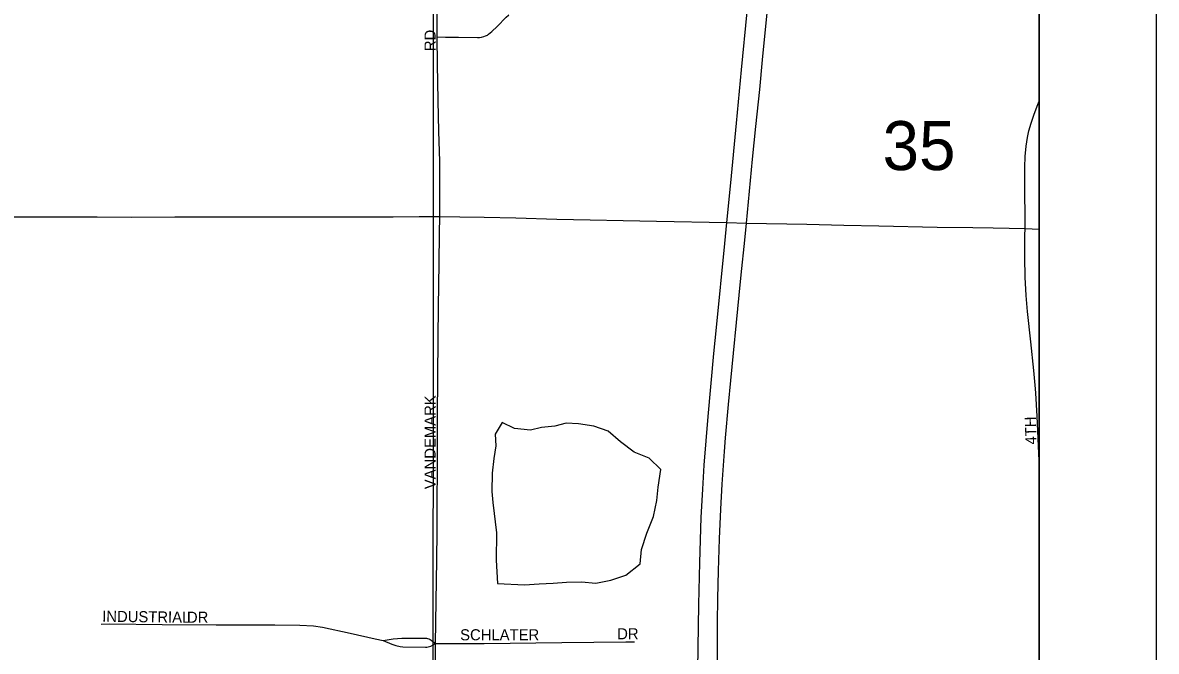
# Model space of a CAD drawing. Extents: x 0 to 1391, y -24 to 440.
# Drawn here: x 460.63 to 480, y 332.13 to 342.87 of the extents above; entities that cross this region are included whole.
import ezdxf

# ---------------------------------------------------------------- set-up
doc = ezdxf.new("R2010")
doc.units = 0
for name, color, linetype in [('GM_X_City_Street', 7, 'Continuous'), ('GM_X_City_Street_Text', 7, 'Continuous'), ('GM_X_Corporation', 7, 'Continuous'), ('GM_X_Interstate_Route', 7, 'Continuous'), ('GM_X_Minor_Lake', 7, 'Continuous'), ('GM_X_Section', 7, 'Continuous'), ('GM_X_Section_Text', 7, 'Continuous'), ('GM_X_Township', 7, 'Continuous'), ('SH_Data', 7, 'Continuous')]:
    doc.layers.add(name, color=color, linetype=linetype)

msp = doc.modelspace()

# ---------------------------------------------------------------- linework, layer by layer
at = {"layer": 'GM_X_City_Street'}
for points in [[(467.717, 342.622), (467.717, 343.089)], [(467.717, 342.622), (467.859, 342.62), (468.078, 342.616), (468.404, 342.611), (468.439, 342.612), (468.471, 342.616), (468.51, 342.627), (468.543, 342.639), (468.573, 342.654), (468.594, 342.668), (468.65, 342.712), (468.74, 342.797), (468.895, 342.96), (468.935, 342.994), (468.941, 342.997)], [(467.761, 339.554), (467.762, 339.75), (467.76, 340.046), (467.758, 340.5), (467.744, 341.008), (467.734, 341.536), (467.722, 342.157), (467.717, 342.616), (467.717, 342.622)], [(477.757, 339.347), (477.758, 339.525), (477.753, 339.997), (477.754, 340.395), (477.762, 340.582), (477.778, 340.757), (477.8, 340.905), (477.824, 341.015), (477.86, 341.148), (477.911, 341.303), (477.974, 341.466), (478, 341.523)], [(459.98, 339.55), (460.352, 339.55), (460.948, 339.551), (461.483, 339.549), (461.906, 339.546), (462.489, 339.542), (463.234, 339.548), (464.689, 339.549), (465.111, 339.548), (465.608, 339.547), (466.962, 339.551), (467.41, 339.554), (467.761, 339.554)], [(467.688, 332.258), (467.7, 332.981), (467.708, 333.682), (467.713, 334.18), (467.72, 335.738), (467.723, 336.135), (467.73, 337.48), (467.736, 338.01), (467.748, 338.755), (467.755, 339.262), (467.761, 339.554)], [(467.761, 339.554), (468.101, 339.551), (468.516, 339.543), (469.058, 339.531), (469.757, 339.511), (471.459, 339.475), (472.665, 339.45), (472.999, 339.443), (474.031, 339.425), (474.664, 339.408), (475.261, 339.394), (476.254, 339.374), (476.864, 339.364), (477.21, 339.363), (477.757, 339.347)], [(477.942, 336.538), (477.938, 336.612), (477.91, 336.921), (477.857, 337.415), (477.801, 337.934), (477.778, 338.207), (477.762, 338.518), (477.754, 338.854), (477.756, 339.227), (477.757, 339.347)], [(477.757, 339.347), (478, 339.337)], [(478, 335.321), (477.998, 335.381), (477.964, 336.141), (477.942, 336.538)], [(461.975, 332.591), (462.123, 332.594), (463.017, 332.583), (463.937, 332.579), (464.944, 332.58), (465.366, 332.576), (465.6, 332.561), (465.758, 332.539), (466.231, 332.436), (466.657, 332.343), (466.795, 332.312)], [(466.795, 332.312), (466.965, 332.34), (467.113, 332.352), (467.306, 332.351), (467.509, 332.351), (467.53, 332.35), (467.548, 332.346), (467.572, 332.338), (467.595, 332.328), (467.611, 332.318), (467.688, 332.258)], [(466.795, 332.312), (466.94, 332.25), (467.01, 332.226), (467.082, 332.209), (467.131, 332.204), (467.513, 332.199), (467.537, 332.2), (467.559, 332.203), (467.585, 332.21), (467.604, 332.216), (467.688, 332.258)], [(467.663, 329.897), (467.672, 330.736), (467.675, 331.091), (467.688, 332.246), (467.688, 332.258)], [(467.688, 332.258), (467.782, 332.258), (468.515, 332.261), (469.845, 332.279), (470.938, 332.288), (471.087, 332.288)]]:
    msp.add_lwpolyline(points, dxfattribs=at)
at = {"layer": 'GM_X_Corporation'}
msp.add_line((478, 308.53), (478, 378.802), dxfattribs=at)
at = {"layer": 'GM_X_Interstate_Route'}
for points in [[(472.17, 331.818), (472.183, 332.924), (472.199, 333.644), (472.226, 334.414), (472.251, 334.897), (472.278, 335.306), (472.345, 336.136), (472.441, 337.213), (472.485, 337.658), (472.63, 339.092), (472.665, 339.45), (472.731, 340.131), (472.827, 341.146), (472.913, 342.062), (473.013, 343.051)], [(472.501, 331.638), (472.502, 332.135), (472.505, 332.62), (472.511, 333.03), (472.52, 333.502), (472.536, 334.049), (472.561, 334.558), (472.584, 334.98), (472.623, 335.539), (472.641, 335.774), (472.691, 336.344), (472.73, 336.752), (472.874, 338.211), (472.91, 338.557), (472.969, 339.151), (472.999, 339.443), (473.102, 340.536), (473.158, 341.093), (473.224, 341.723), (473.275, 342.23), (473.35, 343.034)]]:
    msp.add_lwpolyline(points, dxfattribs=at)
at = {"layer": 'GM_X_Minor_Lake'}
for points in [[(468.746, 333.288), (469.208, 333.265), (469.459, 333.282), (469.695, 333.293), (469.923, 333.311), (470.182, 333.313), (470.425, 333.293), (470.684, 333.341), (470.936, 333.427), (471.183, 333.619), (471.203, 333.868), (471.299, 334.147), (471.41, 334.432), (471.468, 334.704), (471.488, 334.93), (471.538, 335.232), (471.337, 335.426), (471.08, 335.529), (470.848, 335.708), (470.638, 335.887), (470.389, 335.975), (470.131, 336.011), (469.918, 336.022), (469.727, 335.973), (469.499, 335.948), (469.308, 335.906), (469.035, 335.934), (468.824, 336.037), (468.706, 335.835), (468.718, 335.638), (468.684, 335.419), (468.657, 335.169), (468.651, 334.859), (468.663, 334.669)], [(468.663, 334.669), (468.73, 334.153), (468.721, 333.683), (468.746, 333.288)]]:
    msp.add_lwpolyline(points, dxfattribs=at)
at = {"layer": 'GM_X_Section'}
msp.add_line((478, 329.504), (478, 349.585), dxfattribs=at)
msp.add_lwpolyline([(467.652, 349.609), (467.641, 329.557), (447.102, 329.433), (447.184, 349.582)], close=True, dxfattribs=at)
msp.add_lwpolyline([(478, 349.585), (467.652, 349.609), (467.641, 329.557), (478, 329.504)], dxfattribs=at)
at = {"layer": 'GM_X_Township'}
msp.add_lwpolyline([(478, 305.116), (478, 388.948)], dxfattribs=at)
at = {"layer": 'SH_Data'}
for p, q in [((480, 420), (480, 280)), ((478, 418), (478, 282))]:
    msp.add_line(p, q, dxfattribs=at)

# ---------------------------------------------------------------- texts
at = {"layer": 'GM_X_City_Street_Text'}
for s, rotation, p in [('RD', 90, (467.688, 342.379)), ('VANDEMARK', 90, (467.688, 334.896)), ('4TH', 91.6357, (477.955, 335.662)), ('INDUSTRIAL', 359.3094, (461.991, 332.632)), ('DR', 0, (463.44, 332.615)), ('DR', 0, (470.79, 332.332)), ('SCHLATER', 0, (468.107, 332.315))]:
    msp.add_text(s, height=0.1894, rotation=rotation, dxfattribs=at).set_placement(p)
at = {"layer": 'GM_X_Section_Text'}
msp.add_text('35', height=0.8371, rotation=0, dxfattribs=at).set_placement((475.324, 340.347))

doc.saveas('drawing.dxf')
